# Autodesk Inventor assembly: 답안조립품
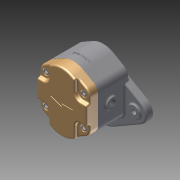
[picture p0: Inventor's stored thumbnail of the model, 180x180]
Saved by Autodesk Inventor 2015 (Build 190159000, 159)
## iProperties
Created: 2025-11
Part Number: 답안조립품
Document SubType Name: Assembly
Designer: user
Author: user
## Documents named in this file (11)
- C:\Users\user\Desktop\751103V1015 (2)\답안조립품.iam
- C:\Users\user\Desktop\751103V1015\가져온 구성요소\3자 실링\3자 실링.ipt
- C:\Users\user\Desktop\751103V1015\가져온 구성요소\6각 구멍붙이 볼트 M6x16\6각 구멍붙이 볼트 M6x16.ipt
- C:\Users\user\Desktop\751103V1015\가져온 구성요소\DU 부시\DU 부시.ipt
- C:\Users\user\Desktop\751103V1015\가져온 구성요소\가이드 블록\가이드 블록.ipt
- C:\Users\user\Desktop\751103V1015\가져온 구성요소\구동기어\구동기어.ipt
- C:\Users\user\Desktop\751103V1015\가져온 구성요소\스퍼기어\스퍼기어.ipt
- C:\Users\user\Desktop\751103V1015\가져온 구성요소\실링\실링.ipt
- C:\Users\user\Desktop\751103V1015\가져온 구성요소\오일 실 16 30 7\오일 실 16 30 7.ipt
- C:\Users\user\Desktop\751103V1015\가져온 구성요소\커버\커버.ipt
- C:\Users\user\Desktop\751103V1015\본체.ipt
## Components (11 placed, 5 different names)
1. 3자 실링:1
2. DU 부시:1
3. 가이드 블록:1
4. 구동기어:1
5. DU 부시:2
6. DU 부시:3
7. DU 부시:4
8. 6각 구멍붙이 볼트 M6x16:1
9. 6각 구멍붙이 볼트 M6x16:2
10. 6각 구멍붙이 볼트 M6x16:3
11. 6각 구멍붙이 볼트 M6x16:4
